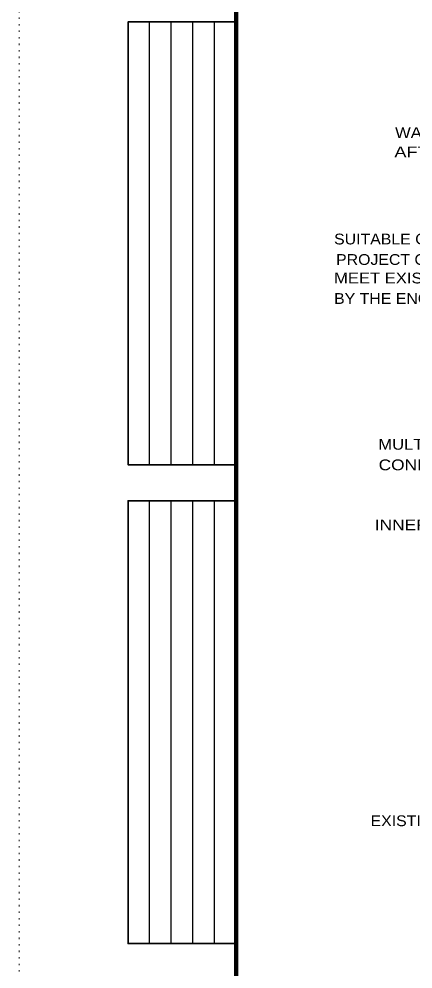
# Model space of a CAD drawing. Extents: x 312583 to 312854, y 144419 to 144597.
# Drawn here: x 312601.2 to 312629, y 144455.1 to 144522.1 of the extents above; entities that cross this region are included whole.
import ezdxf

# ---------------------------------------------------------------- set-up
doc = ezdxf.new("R2010")
doc.units = 0
doc.header["$LTSCALE"] = 0.3
doc.linetypes.add('DOTTED', pattern=[1.5, 0.3, -1.2])
doc.layers.add('1', color=7, linetype='Continuous', lineweight=13)
doc.layers.add('62', color=7, linetype='DOTTED', lineweight=13)

msp = doc.modelspace()

# ---------------------------------------------------------------- linework, layer by layer
at = {"layer": '1', "lineweight": 25}
for p, q in [((312610.4087, 144490.6573), (312610.4087, 144521.8756)), ((312611.9315, 144490.6573), (312611.9315, 144521.8756)), ((312613.4543, 144490.6573), (312613.4543, 144521.8756)), ((312614.9772, 144490.6573), (312614.9772, 144521.8756)), ((312610.4087, 144456.901), (312610.4087, 144488.1192)), ((312611.9315, 144456.901), (312611.9315, 144488.1192)), ((312613.4543, 144456.901), (312613.4543, 144488.1192)), ((312614.9772, 144456.901), (312614.9772, 144488.1192))]:
    msp.add_line(p, q, dxfattribs=at)
at = {"layer": '1', "lineweight": 158}
msp.add_lwpolyline([(312616.5, 144423.1446), (312616.5, 144585.0846), (312849, 144585.0846)], dxfattribs=at)
at = {"layer": '1', "lineweight": 35}
for points in [[(312616.5, 144490.6573), (312608.8858, 144490.6573), (312608.8858, 144521.8756), (312616.5, 144521.8756)], [(312616.5, 144456.901), (312608.8858, 144456.901), (312608.8858, 144488.1192), (312616.5, 144488.1192)]]:
    msp.add_lwpolyline(points, dxfattribs=at)
at = {"layer": '62'}
msp.add_line((312601.2, 144418.5846), (312601.2, 144596.7846), dxfattribs=at)

# ---------------------------------------------------------------- texts
at = {"layer": '1'}
for s, width, p in [('WARNING TAPE SHALL BE INSTALLED', 1.15, (312627.7089, 144513.69)), ('AFTER FIRST LIFT. (SEE NOTE 7)', 1.25, (312627.6605, 144512.3301)), ('SUITABLE GRANULAR MATERIAL FROM', 1.1, (312623.4083, 144506.1883)), ('PROJECT OR COURSE AGGREGATE TO', 1.1, (312623.5484, 144504.7439)), ('MEET EXISTING GRADE AS DIRECTED', 1.15, (312623.4083, 144503.4399)), ('BY THE ENGINEER.', 1.1, (312623.4084, 144501.9955)), ('MULTIDUCT RIGID NON-METALLIC', 1.15, (312626.5282, 144491.7177)), ('CONDUIT (SEE NOTES 2 & 14)', 1.2, (312626.5487, 144490.2686)), ('INNER DUCT (SEE DETAIL "A")', 1.2, (312626.2793, 144486.0366)), ('EXISTING PAVEMENT SURFACE', 1.1, (312625.9796, 144465.1801))]:
    msp.add_text(s, height=0.76, dxfattribs=dict(at, width=width)).set_placement(p)

doc.saveas('drawing.dxf')
